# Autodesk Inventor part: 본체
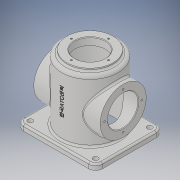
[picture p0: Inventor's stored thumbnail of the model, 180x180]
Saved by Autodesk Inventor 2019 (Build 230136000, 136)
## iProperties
Created: 2020-12
Part Number: 본체
Material: 일반
Document SubType Name: Modeling
Designer: jun-1-14
Density: 1 g/cm^3
Appearance: 기본값
Mass: 457.576 g
Surface Area: 1067.12 cm^2
Volume: 457.576 cm^3
Author: jun-1-14
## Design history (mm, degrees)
sketch "스케치1"
  geometry: L1 (70, -60)-(-70, -60); L2 (-70, -60)-(-70, 60); L3 (-70, 60)-(70, 60); L4 (70, 60)-(70, -60); L5 (70, -60)-(-70, 60); L6 (-70, -60)-(70, 60); 1 further point
  constraints: 12 end point, 2 midpoint, 2 parallel, 1 horizontal, 1 perpendicular
  dimensions: "d0" = 140 distance of L2.end L3.end; "d1" = 120 distance of L1.end L2.end
extrude "돌출1" new body sketch "스케치1" distance "d2" = 10; taper "d3" = 0 deg
fillet "모깎기1" dims "d4" = 12
sketch "스케치2"
  geometry: L1 (-70, 48)-(-70, -48) reference; L2 (58, 60)-(-58, 60) reference; C1 r 4.5 at (-58, 48); 1 further point
  constraints: 1 centre point
  dimensions: "d5" = 9 diameter of C1; "d6" = 12 distance from line of C1.centre L1; "d7" = 12 distance from line of C1.centre L2
extrude "돌출2" cut sketch "스케치2" extent not by distance; stored distance "d8" = 10; taper "d9" = 0 deg
sketch "스케치3"
  geometry: C1 r 50 at (0, 0); 1 further point
  constraints: 1 centre point, 1 coincident
  dimensions: "d10" = 100 diameter of C1
extrude "돌출3" join sketch "스케치3" distance "d11" = 110; taper "d12" = 0 deg
sketch "스케치4"
  geometry: C1 r 41 at (0, 0); 1 further point
  constraints: 1 centre point, 1 coincident
  dimensions: "d13" = 82 diameter of C1
extrude "돌출4" join sketch "스케치4" distance "d14" = 5; taper "d15" = 0 deg
node "작업 평면3"
sketch "스케치5"
  geometry: L1 (0, -48)-(0, 48) reference; C1 r 41 at (60, 0); 2 further points
  constraints: 1 centre point, 1 horizontal alignment, 1 midpoint
  dimensions: "d18" = 82 diameter of C1; "d19" = 60 distance from line of L1 C1.centre
extrude "돌출5" join sketch "스케치5" stored distance "d20" = 15; taper "d21" = 0 deg
sketch "스케치6"
  geometry: C1 r 41 at (0, 0) reference; C2 r 27 at (0, 0); 1 further point
  constraints: 1 centre point, 1 coincident
  dimensions: "d22" = 54 diameter of C2
extrude "돌출6" cut sketch "스케치6" extent not by distance; stored distance "d23" = 15; taper "d24" = 0 deg
node "작업 평면4"
sketch "스케치8"
  geometry: L1 (58, -10)-(-58, -10) reference; 3 further points
  constraints: 1 midpoint, 1 vertical alignment, 1 other
  dimensions: "d28" = 70 distance from line of L1 point (0, 60)
feature "엠보싱1" sketch "스케치8" dims "d0" = 140, "d1" = 120, "d29" = 0.5, "d30" = 0
sketch "스케치9"
  geometry: C1 r 41 at (0, 0) reference; 2 further points
  constraints: 1 vertical alignment
  dimensions: "d31" = 33 distance of C1.centre point (0, 33)
hole "구멍1" sketch "스케치9" at (0, 33) diameter "d32" = 3.242; stored, may be unused: countersink angle "d36" = 90 deg, drill point angle "d38" = 118 deg; dims "d33" = 8, "d34" = 4, "d35" = 2, "d37" = 10
fillet "모깎기2" dims "d53" = 6
fillet "모깎기3" dims "d54" = 3
fillet "모깎기4" dims "d55" = 3
chamfer "모따기1" distance "d56" = 1; stored, may be unused: second distance "d57" = 2, angle "d58" = 45 deg
sketch "스케치11"
  geometry: C1 r 41 at (0, 0) reference; C2 r 27 at (0, 0); 1 further point
  constraints: 1 centre point, 1 coincident
  dimensions: "d59" = 54 diameter of C2
extrude "돌출8" cut sketch "스케치11" distance "d60" = 13; taper "d61" = 0 deg
node "작업 평면5"
sketch "스케치12"
  geometry: C1 r 42 at (0, 0); 1 further point
  constraints: 1 centre point, 1 coincident
  dimensions: "d63" = 84 diameter of C1
extrude "돌출9" cut sketch "스케치12" extent not by distance; stored distance "d64" = 13; taper "d65" = 0 deg
fillet "모깎기5" dims "d66" = 3
sketch "스케치14"
  geometry: C1 r 41 at (0, 0) reference; 2 further points
  constraints: 1 vertical alignment
  dimensions: "d67" = 33 distance of point (0, 0) point (0, 33)
hole "구멍3" sketch "스케치14" at (0, 33) diameter "d68" = 3.242; stored, may be unused: countersink angle "d72" = 90 deg, drill point angle "d74" = 118 deg; dims "d69" = 8, "d70" = 4, "d71" = 2, "d73" = 10
chamfer "모따기2" distance "d78" = 1; stored, may be unused: second distance "d79" = 2, angle "d80" = 45 deg
fillet "모깎기6" dims "d81" = 3
node "솔리드1"
mirror "미러1"
mirror "미러2"
mirror "미러3"
pattern_circular "원형 패턴1" dims angle "d40" = 360 deg
mirror "미러4"
pattern_circular "원형 패턴3" dims angle "d76" = 360 deg
other parameters: "d17" = 59, "d62" = -13
